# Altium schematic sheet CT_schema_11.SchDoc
size 387 x 385 mm
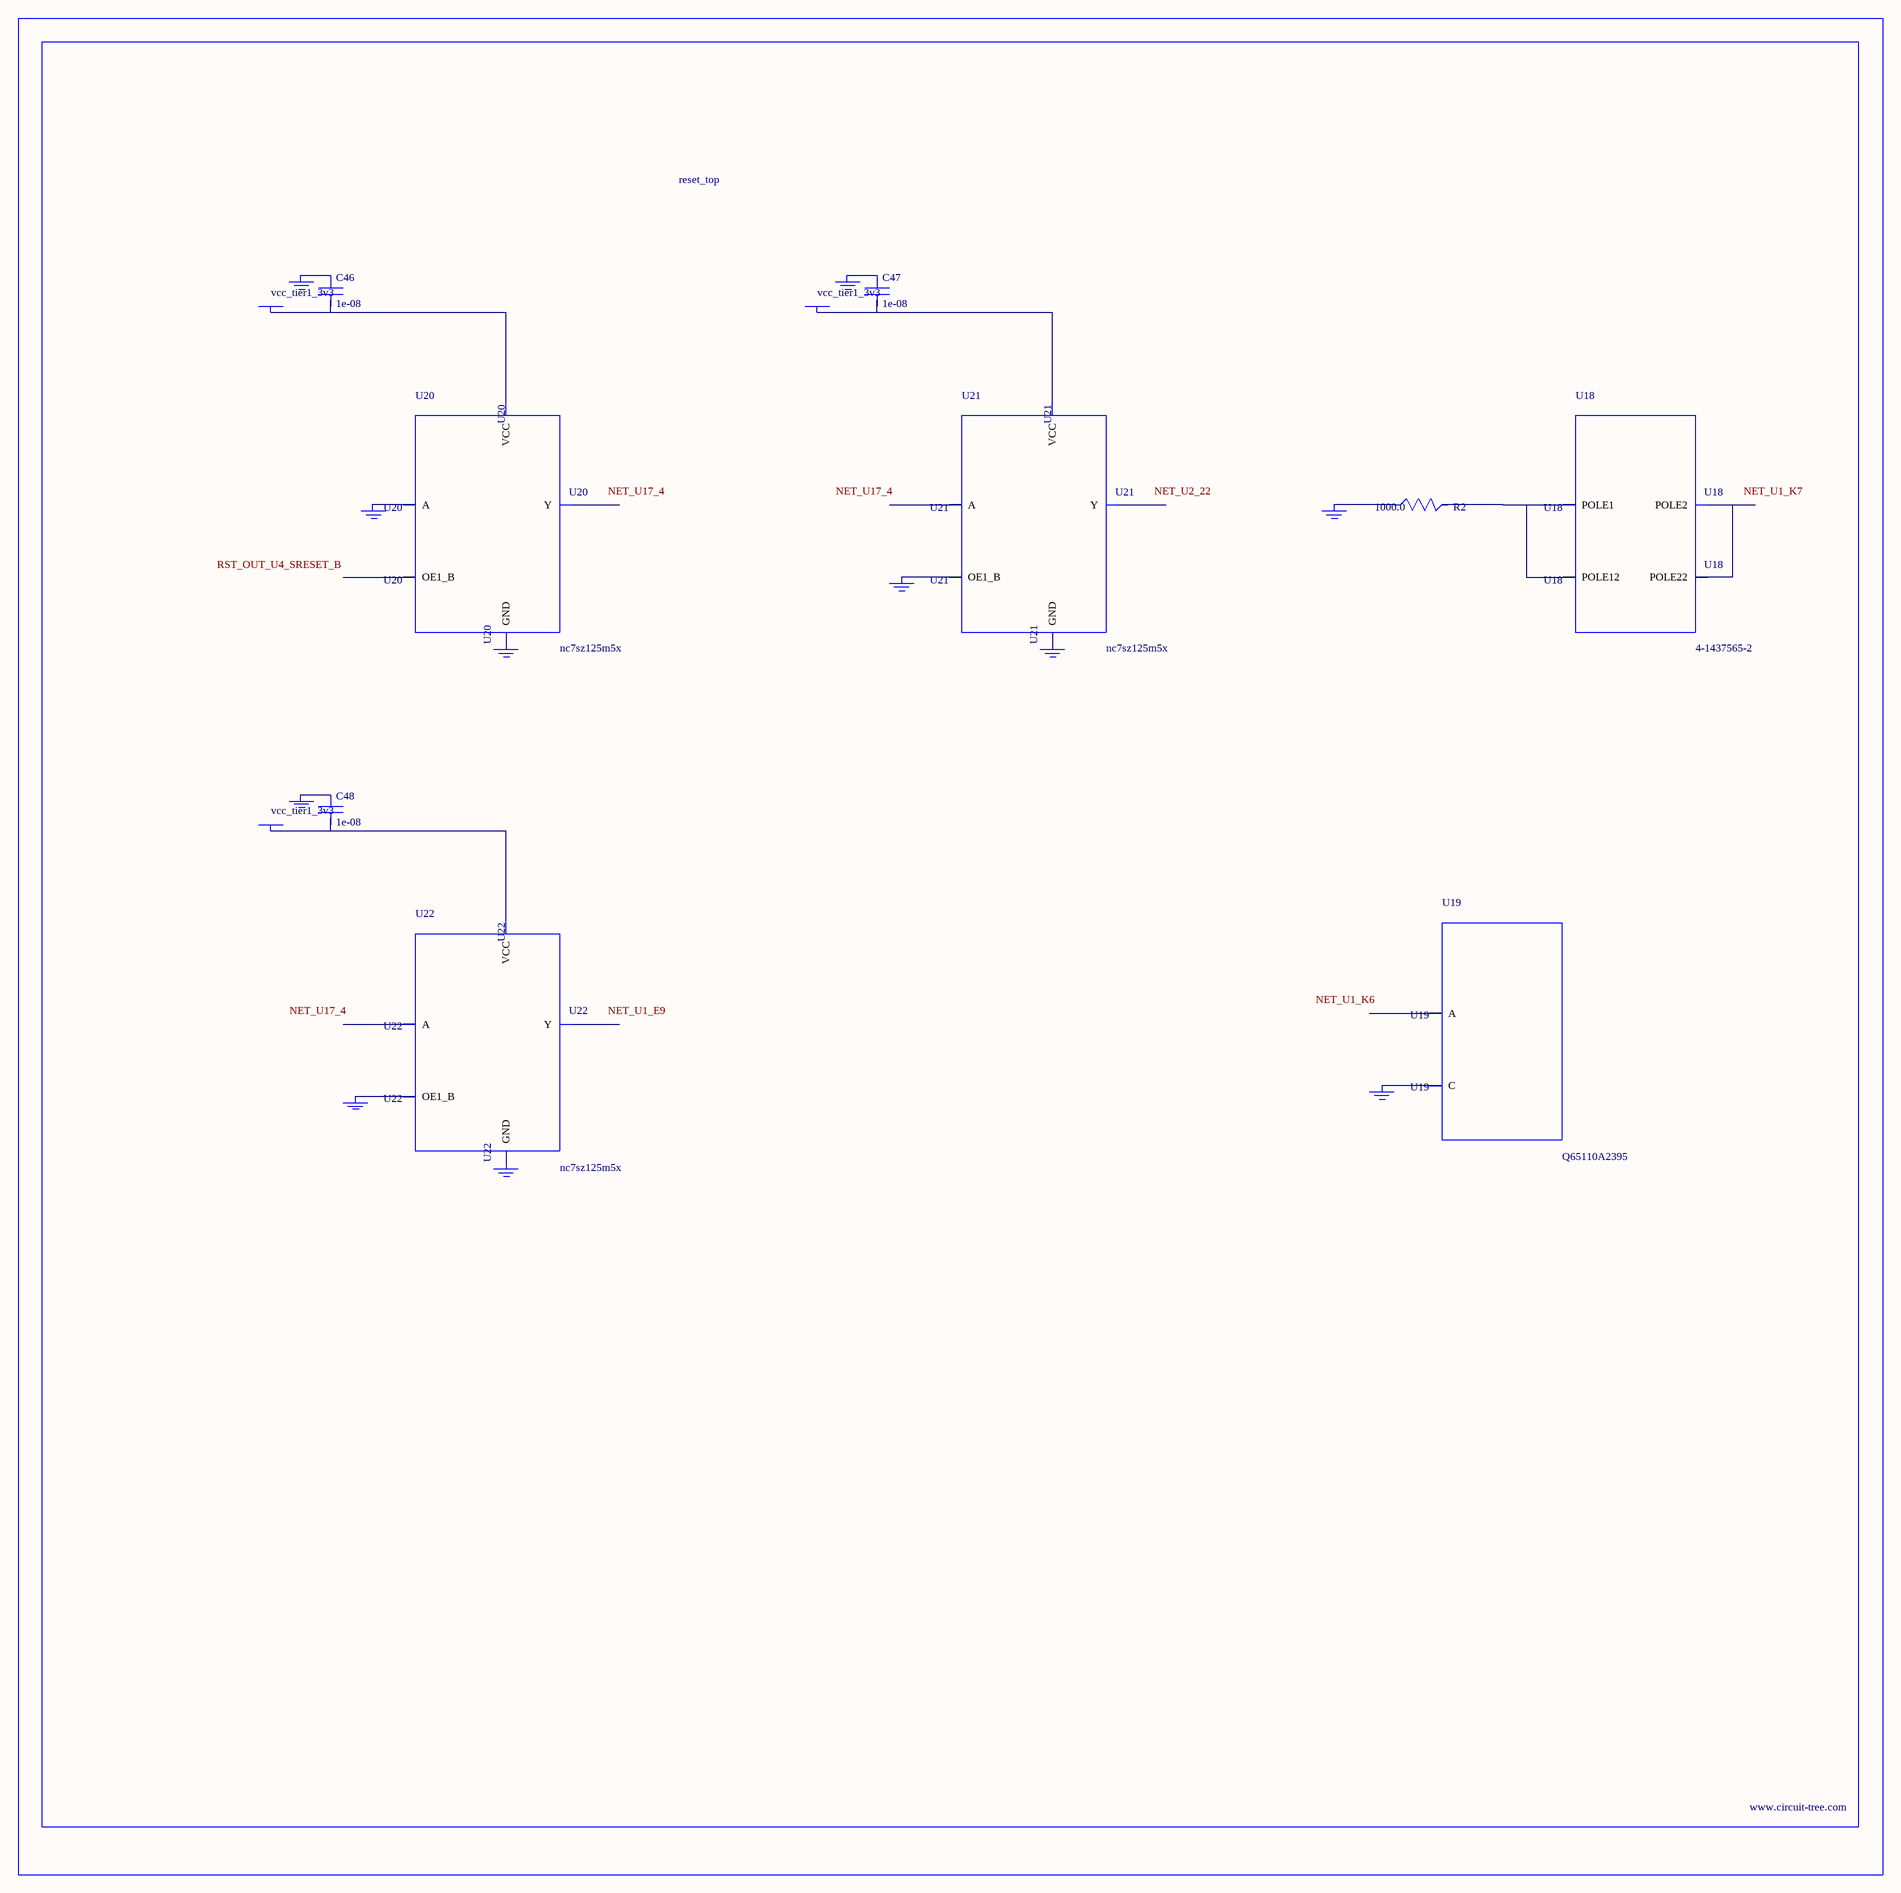
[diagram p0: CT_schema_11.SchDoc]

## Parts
BORDER10  (no value)
C46  1e-08  [C0402]
C47  1e-08  [C0402]
C48  1e-08  [C0402]
GND_INSTANCE_10_0  (no value)
GND_INSTANCE_10_1  (no value)
GND_INSTANCE_10_2  (no value)
GND_INSTANCE_10_3  (no value)
GND_INSTANCE_10_4  (no value)
GND_INSTANCE_10_5  (no value)
GND_INSTANCE_10_6  (no value)
GND_INSTANCE_10_7  (no value)
GND_INSTANCE_10_8  (no value)
GND_INSTANCE_10_9  (no value)
GND_INSTANCE_10_10  (no value)
POWER_INSTANCE_10_0  vcc_tier1_3v3
POWER_INSTANCE_10_1  vcc_tier1_3v3
POWER_INSTANCE_10_2  vcc_tier1_3v3
R2  1000.0  [R0603]
U18  4-1437565-2  [SW_4-1437565-2]
U19  Q65110A2395  [LGM67K-G1J2-24-Z]
U20  nc7sz125m5x  [NC7SZ125M5X]
U21  nc7sz125m5x  [NC7SZ125M5X]
U22  nc7sz125m5x  [NC7SZ125M5X]

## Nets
NetC46_1: C46.1 GND_INSTANCE_10_2.0(GND)
NetC46_2: C46.2 POWER_INSTANCE_10_0.0(PWR) U20.5(VCC)
NetC47_1: C47.1 GND_INSTANCE_10_5.0(GND)
NetC47_2: C47.2 POWER_INSTANCE_10_1.0(PWR) U21.5(VCC)
NetC48_1: C48.1 GND_INSTANCE_10_8.0(GND)
NetC48_2: C48.2 POWER_INSTANCE_10_2.0(PWR) U22.5(VCC)
NetGND_INSTANCE_10_0_0: GND_INSTANCE_10_0.0(GND) R2.1
NetGND_INSTANCE_10_1_0: GND_INSTANCE_10_1.0(GND) U19.C
NetGND_INSTANCE_10_3_0: GND_INSTANCE_10_3.0(GND) U20.2(A)
NetGND_INSTANCE_10_4_0: GND_INSTANCE_10_4.0(GND) U20.3(GND)
NetGND_INSTANCE_10_6_0: GND_INSTANCE_10_6.0(GND) U21.1(OE1_B)
NetGND_INSTANCE_10_7_0: GND_INSTANCE_10_7.0(GND) U21.3(GND)
NetGND_INSTANCE_10_9_0: GND_INSTANCE_10_9.0(GND) U22.1(OE1_B)
NetGND_INSTANCE_10_10_0: GND_INSTANCE_10_10.0(GND) U22.3(GND)
NetR2_2: R2.2 U18.1(POLE1) U18.2(POLE12)
NetU18_3: U18.3(POLE2) U18.4(POLE22)

Not connected (* = marked no-connect by the designer): U19 A; U20 1(OE1_B) 4(Y); U21 2(A) 4(Y); U22 2(A) 4(Y)

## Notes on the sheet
- Labels drawn without touching a wire or pin: NET_U1_E9, NET_U1_K6, NET_U1_K7, NET_U2_22, NET_U17_4, RST_OUT_U4_SRESET_B

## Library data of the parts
BORDER10 = BORDER_PAGE10
C46-C48 = C0402C103K3RAC
GND_INSTANCE_10_0-GND_INSTANCE_10_10 = GND
POWER_INSTANCE_10_0-POWER_INSTANCE_10_2 = PWR
R2 = RC0603JR-071KL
